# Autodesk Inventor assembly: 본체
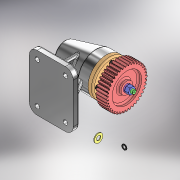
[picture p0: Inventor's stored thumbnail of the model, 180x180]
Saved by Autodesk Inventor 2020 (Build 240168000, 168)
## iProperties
Created: 2024-12
Part Number: 본체
Document SubType Name: Assembly
Designer: 1강의실14
Author: 1강의실14
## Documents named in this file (14)
- C:\Users\1강의실14\Desktop\741204V1001\본체.iam
- C:\Users\1강의실14\Desktop\741204V1001\본체.ipt
- C:\Users\1강의실14\Desktop\741204V1001\앵귤러 볼 베어링 7003A.ipt
- C:\Users\1강의실14\Desktop\741204V1001\앵귤러 볼 제어링 7204A.ipt
- C:\Users\1강의실14\Desktop\741204V1001\축.ipt
- C:\Users\1강의실14\Desktop\741204V1001\커버.ipt
- C:\Users\1강의실14\Desktop\741204V1001\평행 키 4x4x14.ipt
- C:\Users\1강의실14\Desktop\741204V1001\평와셔 M8.ipt
- C:\Users\1강의실14\Desktop\741204V1001\스퍼기어.ipt
- C:\Users\1강의실14\Desktop\741204V1001\스프링 와셔 M8.ipt
- C:\Users\1강의실14\Desktop\741204V1001\오일 실 20 32 8.ipt
- C:\Users\1강의실14\Desktop\741204V1001\육각 소켓 머리 볼트 M4x10.ipt
- C:\Users\1강의실14\Desktop\741204V1001\육각 너트 M8.ipt
- C:\Users\1강의실14\Desktop\741204V1001\실링.ipt
